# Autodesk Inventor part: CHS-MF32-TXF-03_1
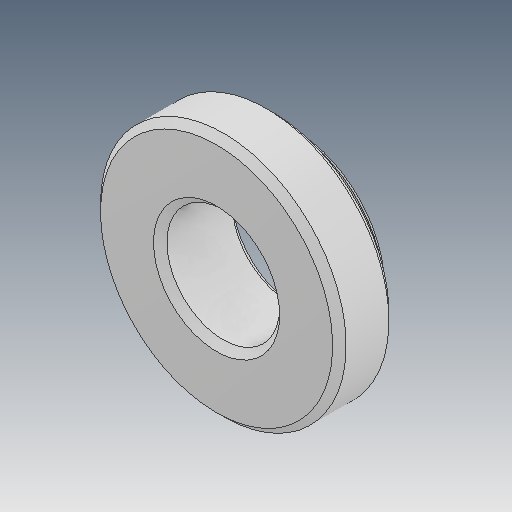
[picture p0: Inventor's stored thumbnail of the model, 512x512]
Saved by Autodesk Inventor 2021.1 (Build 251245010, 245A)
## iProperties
Created: 2021-05
Part Number: CHS-MF32-TXF-03_1
Material: Ogólny
Document SubType Name: Modeling
Designer: user
Density: 1 g/cm^3
Appearance: Domyślna
Author: user
Revision Number: ÈÎºÎ
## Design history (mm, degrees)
feature "ÊäÈë1"
node "Bryła1"
